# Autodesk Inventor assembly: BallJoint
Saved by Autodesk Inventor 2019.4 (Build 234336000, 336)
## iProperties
Created: 2020-02
Part Number: BallJoint
Document SubType Name: Assembly
Designer: Administrator
Title: BallJoint v14
Author: Administrator
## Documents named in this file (3)
- c:\worker\convert-fusion-r01\tmp\job-1\5\output\files\e4333473-a38b-4431-9958-ad24a2f67704\BallJoint v14_5.iam
- c:\worker\convert-fusion-r01\tmp\job-1\5\output\files\e4333473-a38b-4431-9958-ad24a2f67704\Component1_1.ipt
- c:\worker\convert-fusion-r01\tmp\job-1\5\output\files\e4333473-a38b-4431-9958-ad24a2f67704\Component2_1.ipt
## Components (2 placed, 2 different names)
1. Component1:1
2. Component2:1
